// Mitsubishi GX Works2 project: 3 - 副本   PLC: FX1S

PROGRAM MAIN
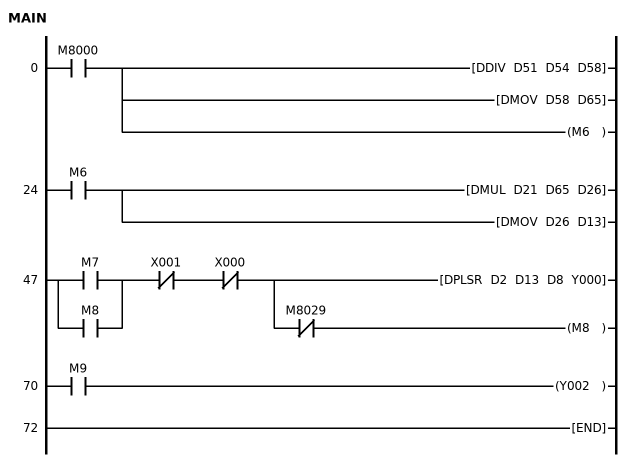
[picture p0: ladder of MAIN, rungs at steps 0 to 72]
0     LD      M8000
      DDIV    D51 D54 D58
      DMOV    D58 D65
      OUT     M6
24    LD      M6
      DMUL    D21 D65 D26
      DMOV    D26 D13
47    LD      M7
      OR      M8
      ANI     X001
      ANI     X000
      DPLSR   D2 D13 D8 Y000
      ANI     M8029
      OUT     M8
70    LD      M9
      OUT     Y002
72    END
END_PROGRAM
